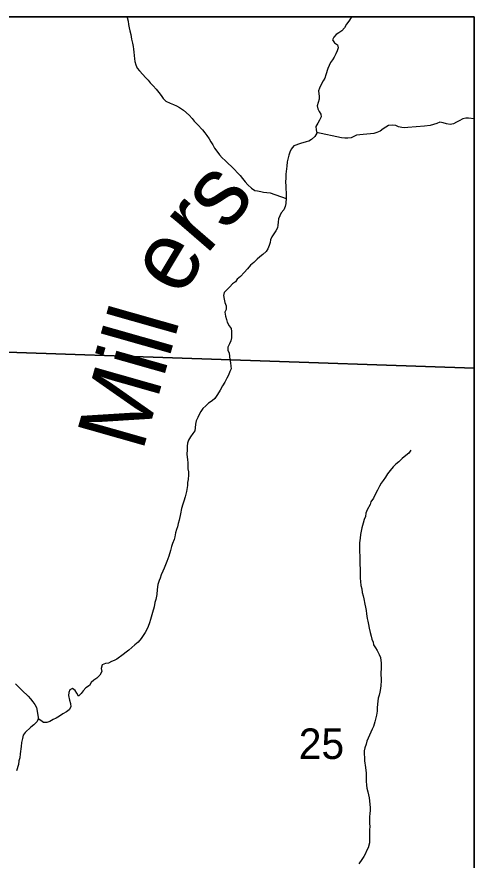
# Model space of a CAD drawing. Extents: x -3.3 to 34, y 0 to 56.8.
# Drawn here: x 2.868 to 3.496, y 33.719 to 34.877 of the extents above; entities that cross this region are included whole.
import ezdxf

# ---------------------------------------------------------------- set-up
doc = ezdxf.new("R2010")
doc.units = 0
for name, color, linetype in [('GM_X_Corporation', 7, 'Continuous'), ('GM_X_Section_Text', 7, 'Continuous'), ('GT_Project_Cells', 7, 'Continuous'), ('GT_Project_Soil_Layers', 7, 'Continuous'), ('SH_Data', 7, 'Continuous')]:
    doc.layers.add(name, color=color, linetype=linetype)

msp = doc.modelspace()

# ---------------------------------------------------------------- linework, layer by layer
at = {"layer": 'GM_X_Corporation'}
for points in [[(3.4961, 33.3748), (3.4961, 34.8771), (1.8402, 34.8771), (1.8394, 34.8565), (1.8337, 34.7226), (1.8165, 34.1713), (1.798, 33.5922), (1.7901, 33.4394), (2.0441, 33.4254), (2.4136, 33.4064), (2.6471, 33.398), (2.8087, 33.3951), (3.4269, 33.3772)], [(3.4961, 34.395), (3.4961, 34.8771), (2.8108, 34.8771), (2.8008, 34.4185)], [(3.4961, 33.376), (3.4961, 34.395), (2.8008, 34.4185), (2.7828, 33.3964)]]:
    msp.add_lwpolyline(points, close=True, dxfattribs=at)
at = {"layer": 'GT_Project_Soil_Layers'}
for points in [[(3.0195, 34.8771), (3.0197, 34.8762), (3.0209, 34.8713), (3.0217, 34.8667), (3.0225, 34.8618), (3.0233, 34.858), (3.0245, 34.8527), (3.0258, 34.8463), (3.027, 34.841), (3.0278, 34.8364), (3.0282, 34.8327), (3.029, 34.8285), (3.0299, 34.8194), (3.0303, 34.8156), (3.0315, 34.8114), (3.0335, 34.8065), (3.0366, 34.8028), (3.0412, 34.7979), (3.0447, 34.7938), (3.0485, 34.79), (3.0512, 34.7863), (3.0555, 34.7822), (3.0597, 34.7777), (3.0632, 34.7732), (3.0663, 34.769), (3.069, 34.7649), (3.0728, 34.7615), (3.0785, 34.7586), (3.0831, 34.7567), (3.0873, 34.7549), (3.0915, 34.7527), (3.0969, 34.7489), (3.1046, 34.7422), (3.1088, 34.7377), (3.1115, 34.734), (3.1161, 34.7295), (3.1231, 34.722), (3.1265, 34.7178), (3.1292, 34.7141), (3.1323, 34.7096), (3.1347, 34.7054), (3.1374, 34.7013), (3.1397, 34.6968), (3.1428, 34.6926), (3.1463, 34.6877), (3.1501, 34.6836), (3.1544, 34.6799), (3.167, 34.6675), (3.1713, 34.663), (3.1747, 34.6593), (3.1782, 34.6552), (3.1817, 34.6506), (3.1855, 34.6465), (3.1902, 34.6417), (3.1948, 34.6387), (3.1986, 34.638), (3.2031, 34.6373), (3.2069, 34.6366), (3.2115, 34.6359), (3.2161, 34.6355), (3.2381, 34.6277)], [(3.3276, 34.8771), (3.3273, 34.8761), (3.3239, 34.8711), (3.3209, 34.8669), (3.3183, 34.8619), (3.3146, 34.8577), (3.3104, 34.855), (3.3067, 34.853), (3.3033, 34.8492), (3.3018, 34.8454), (3.3045, 34.8413), (3.3084, 34.8386), (3.3092, 34.8345), (3.3081, 34.8303), (3.3063, 34.8261), (3.3037, 34.8219), (3.3014, 34.8181), (3.2988, 34.8142), (3.297, 34.8104), (3.2951, 34.8062), (3.2926, 34.7975), (3.2911, 34.7929), (3.2889, 34.7891), (3.2863, 34.7849), (3.2837, 34.7791), (3.2826, 34.7753), (3.2835, 34.7677), (3.2835, 34.7639), (3.2817, 34.7594), (3.2806, 34.7548), (3.2814, 34.751), (3.2833, 34.7472), (3.2857, 34.7435), (3.2861, 34.7397), (3.2839, 34.7351), (3.2813, 34.7313), (3.2787, 34.7267), (3.2791, 34.7221), (3.2799, 34.7176), (3.2773, 34.713), (3.2728, 34.7088), (3.2691, 34.7065), (3.2653, 34.7056), (3.2577, 34.7033), (3.2486, 34.7001), (3.2449, 34.6955), (3.2431, 34.6913)], [(3.4961, 34.737), (3.4885, 34.7382), (3.4847, 34.7382), (3.4806, 34.737), (3.4757, 34.7342), (3.4719, 34.7323), (3.4677, 34.73), (3.4632, 34.7295), (3.4582, 34.7302), (3.4537, 34.7317), (3.4491, 34.7324), (3.4449, 34.7308), (3.4404, 34.7292), (3.4359, 34.728), (3.4279, 34.7272), (3.4051, 34.725), (3.401, 34.7249), (3.3968, 34.7252), (3.3922, 34.7259), (3.3884, 34.7278), (3.3835, 34.7285), (3.3785, 34.728), (3.3748, 34.7257), (3.371, 34.7234), (3.3669, 34.7203), (3.3623, 34.7183), (3.3582, 34.7171), (3.3536, 34.7163), (3.3438, 34.7154), (3.3347, 34.7145), (3.3309, 34.713), (3.3271, 34.711), (3.3226, 34.7106), (3.3184, 34.7105), (3.3138, 34.7108), (3.2798, 34.7181)], [(3.2431, 34.6913), (3.2416, 34.6871), (3.2394, 34.678), (3.2388, 34.6719), (3.2374, 34.6613), (3.2374, 34.6559), (3.2371, 34.6502), (3.2376, 34.6453), (3.2376, 34.64), (3.2381, 34.6362), (3.2382, 34.6286), (3.2375, 34.621), (3.2368, 34.6165), (3.235, 34.6123), (3.2312, 34.608), (3.2275, 34.5996), (3.2268, 34.5951), (3.2265, 34.5913), (3.2262, 34.5875), (3.2239, 34.5833), (3.221, 34.5794), (3.2184, 34.5749), (3.2165, 34.571), (3.2158, 34.5672), (3.2147, 34.5634), (3.2129, 34.5588), (3.2106, 34.555), (3.2058, 34.5508), (3.202, 34.5477), (3.1983, 34.5442), (3.1934, 34.54), (3.1892, 34.5361), (3.1847, 34.5311), (3.1803, 34.5262), (3.1754, 34.5208), (3.1709, 34.5169), (3.1683, 34.5131), (3.1641, 34.5104), (3.1608, 34.5065), (3.1563, 34.5023), (3.1529, 34.4985), (3.1518, 34.4947), (3.153, 34.4894), (3.1538, 34.4848), (3.1554, 34.4803), (3.1555, 34.4754), (3.1536, 34.4715), (3.1545, 34.4662), (3.156, 34.4617), (3.1572, 34.4579), (3.1599, 34.453), (3.1623, 34.4493), (3.1631, 34.4451), (3.1631, 34.4405), (3.1628, 34.4364), (3.1621, 34.4322), (3.1603, 34.428), (3.158, 34.4234), (3.1581, 34.4196), (3.1597, 34.4154), (3.1605, 34.4067), (3.1617, 34.4022), (3.1622, 34.3976), (3.1626, 34.3938), (3.1607, 34.39), (3.1589, 34.3854), (3.1567, 34.3809), (3.1537, 34.3755), (3.1504, 34.3705), (3.1474, 34.3648), (3.1437, 34.3587), (3.14, 34.3533), (3.1362, 34.3499), (3.1313, 34.3468), (3.1276, 34.3433), (3.1238, 34.3394), (3.1208, 34.3352), (3.1186, 34.3314), (3.1168, 34.3272), (3.1145, 34.3226), (3.1135, 34.3177), (3.1131, 34.3127), (3.1124, 34.3089), (3.1098, 34.3051), (3.1065, 34.3005), (3.1039, 34.2959), (3.1024, 34.2917), (3.1021, 34.2875), (3.1021, 34.283), (3.1018, 34.2761), (3.1023, 34.2693), (3.1028, 34.2648), (3.1028, 34.261), (3.1032, 34.2564), (3.1037, 34.2526), (3.1037, 34.2485), (3.1034, 34.242), (3.1027, 34.2378), (3.1024, 34.2336), (3.101, 34.2256), (3.0992, 34.218)], [(3.4093, 34.2821), (3.4064, 34.2783), (3.4022, 34.2748), (3.3973, 34.2706), (3.3928, 34.2663), (3.3887, 34.2629), (3.385, 34.2594), (3.3808, 34.2544), (3.3771, 34.2498), (3.3745, 34.2452), (3.3712, 34.2406), (3.3685, 34.2368), (3.3663, 34.233), (3.3634, 34.2272), (3.36, 34.2215), (3.3578, 34.2162), (3.3544, 34.2115), (3.3534, 34.2074), (3.3493, 34.2001), (3.3474, 34.1959), (3.3467, 34.1913), (3.3453, 34.1871), (3.3438, 34.1818), (3.342, 34.1757), (3.3409, 34.1708), (3.3402, 34.1666), (3.3395, 34.1612), (3.3388, 34.1552), (3.3389, 34.151), (3.3386, 34.1464), (3.3386, 34.1419), (3.3391, 34.1381), (3.3395, 34.1066), (3.3399, 34.1017), (3.3407, 34.0963), (3.3419, 34.0918), (3.3424, 34.0869), (3.3436, 34.0823), (3.3444, 34.0782), (3.346, 34.071), (3.3468, 34.0668), (3.3476, 34.0623), (3.3481, 34.0577), (3.3493, 34.0513), (3.3501, 34.0475), (3.3509, 34.043), (3.3518, 34.0377), (3.3534, 34.032), (3.3549, 34.0267), (3.3558, 34.0229), (3.3573, 34.0187), (3.3581, 34.015), (3.3605, 34.0108), (3.3628, 34.007), (3.3655, 34.0018), (3.3675, 33.9976), (3.3683, 33.9897), (3.3684, 33.9821), (3.3681, 33.9771), (3.3683, 33.9654), (3.368, 33.9593), (3.3677, 33.9551), (3.3666, 33.9501), (3.3659, 33.946), (3.3644, 33.9418), (3.3637, 33.9376), (3.3634, 33.9334), (3.3631, 33.9285), (3.3627, 33.9239), (3.3621, 33.9182), (3.3599, 33.9091), (3.3577, 33.9029), (3.3562, 33.8991), (3.3507, 33.8869), (3.3489, 33.8827), (3.3478, 33.8785), (3.3459, 33.8736), (3.3452, 33.8694), (3.3449, 33.8656), (3.3454, 33.8595), (3.3454, 33.8557), (3.347, 33.8466), (3.3479, 33.8386), (3.3476, 33.8345), (3.3477, 33.828), (3.3481, 33.8223), (3.3489, 33.8182), (3.3501, 33.8132), (3.3518, 33.8049), (3.3522, 33.8007), (3.353, 33.7958), (3.3535, 33.7916), (3.3535, 33.7878), (3.3528, 33.7829), (3.3525, 33.7791), (3.3525, 33.7753), (3.3522, 33.7696), (3.3527, 33.7658), (3.3524, 33.7609), (3.3525, 33.7476), (3.3522, 33.743)], [(3.0992, 34.218), (3.0974, 34.2123), (3.0959, 34.2081), (3.0945, 34.202), (3.0927, 34.1948), (3.0909, 34.186), (3.0898, 34.1815), (3.0887, 34.1769), (3.0872, 34.1731), (3.0862, 34.1685), (3.0851, 34.1632), (3.084, 34.1594), (3.0818, 34.154), (3.0807, 34.1498), (3.0793, 34.1445), (3.0771, 34.1369), (3.0741, 34.1293), (3.0705, 34.1201), (3.0686, 34.1159), (3.0664, 34.1109), (3.0649, 34.1067), (3.0635, 34.1032), (3.062, 34.0976), (3.061, 34.0911), (3.0603, 34.0839), (3.0589, 34.077), (3.0578, 34.0732), (3.0567, 34.0671), (3.0545, 34.0595), (3.0516, 34.0496), (3.0505, 34.0454), (3.0483, 34.0401), (3.0465, 34.0359), (3.0446, 34.0321), (3.0387, 34.0236), (3.0349, 34.0186), (3.0301, 34.0148), (3.0222, 34.0075), (3.0184, 34.0048), (3.0143, 34.0017), (3.0056, 33.9955), (3.0019, 33.9935), (2.9981, 33.9923), (2.9939, 33.9896), (2.9898, 33.9892), (2.9852, 33.9876), (2.9838, 33.9823), (2.985, 33.9785), (2.982, 33.9735), (2.9779, 33.9693), (2.9741, 33.9666), (2.9704, 33.9631), (2.9678, 33.9593), (2.9629, 33.9558), (2.9591, 33.952), (2.9565, 33.9481), (2.9528, 33.9447), (2.9508, 33.9484), (2.9485, 33.9522), (2.9446, 33.9548), (2.9409, 33.9532), (2.9394, 33.9494), (2.9391, 33.9452), (2.9403, 33.9388), (2.9419, 33.9346), (2.9423, 33.9297), (2.9401, 33.9259), (2.9363, 33.9232), (2.9314, 33.9201), (2.9269, 33.917), (2.9224, 33.9143), (2.9182, 33.9123), (2.9137, 33.9096), (2.9096, 33.9084), (2.905, 33.9083), (2.9012, 33.9113), (2.8973, 33.9135), (2.8959, 33.9097), (2.8914, 33.9051), (2.8876, 33.902), (2.8797, 33.8947), (2.8771, 33.8909), (2.8761, 33.8863), (2.8746, 33.881), (2.8743, 33.8753), (2.8729, 33.8654), (2.8722, 33.8597), (2.8711, 33.8555), (2.8704, 33.8505), (2.8679, 33.8418)], [(2.8663, 33.9614), (2.871, 33.9569), (2.8756, 33.9524), (2.8836, 33.9445), (2.8871, 33.9407), (2.8902, 33.9366), (2.8929, 33.9329), (2.8952, 33.9291), (2.8981, 33.9131)], [(3.3522, 33.743), (3.3508, 33.7365), (3.3485, 33.7323), (3.3467, 33.7285), (3.3445, 33.7243), (3.3419, 33.7201), (3.3378, 33.7143)]]:
    msp.add_lwpolyline(points, dxfattribs=at)
at = {"layer": 'SH_Data'}
for p, q in [((-3.3039, 34.8771), (3.4961, 34.8771)), ((3.4961, 34.8771), (3.4961, 28.0771))]:
    msp.add_line(p, q, dxfattribs=at)

# ---------------------------------------------------------------- texts
at = {"layer": 'GM_X_Section_Text'}
msp.add_text('25', height=0.04186, rotation=0, dxfattribs=at).set_placement((3.2553, 33.8583))
at = {"layer": 'GT_Project_Cells'}
for s, height, rotation, p in [('rs', 0.09468, 49.1341, (3.1279, 34.5493)), ('e', 0.0947, 59.137, (3.094, 34.4902)), ('Mill', 0.09469, 74.1424, (3.0406, 34.2785))]:
    msp.add_text(s, height=height, rotation=rotation, dxfattribs=at).set_placement(p)

doc.saveas('drawing.dxf')
